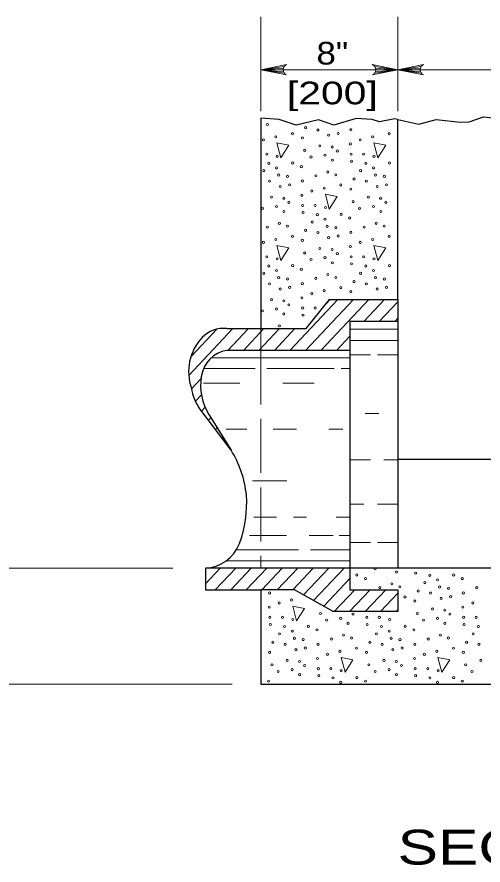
# Model space of a CAD drawing. Extents: x -410.5 to -376.5, y 1617.6 to 1661.6.
# Drawn here: x -396.46 to -393.25, y 1628.9 to 1634.74 of the extents above; entities that cross this region are included whole.
import ezdxf
from ezdxf.enums import TextEntityAlignment as Align

# ---------------------------------------------------------------- set-up
doc = ezdxf.new("R2010")
doc.units = 0
doc.header["$LTSCALE"] = 0.062
doc.linetypes.add('LONG_DASHED', pattern=[7.5, 6, -1.5])
doc.layers.add('1', color=7, linetype='Continuous', lineweight=13)

msp = doc.modelspace()

# ---------------------------------------------------------------- linework, layer by layer
at = {"layer": '1'}
for p, q in [((-394.77725, 1634.09325), (-394.77725, 1634.74117)), ((-393.83325, 1634.09325), (-393.83325, 1634.74117)), ((-394.617, 1634.40017), (-394.77725, 1634.37775)), ((-394.62242, 1634.38908), (-394.77725, 1634.37775)), ((-394.77725, 1634.37775), (-393.83325, 1634.37775)), ((-394.62408, 1634.37775), (-394.77725, 1634.37775)), ((-394.62125, 1634.36333), (-394.77725, 1634.37775)), ((-394.61517, 1634.353), (-394.77725, 1634.37775)), ((-394.06658, 1634.37775), (-393.83325, 1634.37775)), ((-393.99542, 1634.353), (-393.83325, 1634.37775)), ((-393.9935, 1634.40017), (-393.83325, 1634.37775)), ((-393.98925, 1634.36333), (-393.83325, 1634.37775)), ((-393.98808, 1634.38908), (-393.83325, 1634.37775)), ((-393.98642, 1634.37775), (-393.83325, 1634.37775)), ((-393.673, 1634.40017), (-393.83325, 1634.37775)), ((-393.67842, 1634.38908), (-393.83325, 1634.37775)), ((-393.83325, 1634.37775), (-391.91983, 1634.37775)), ((-393.68008, 1634.37775), (-393.83325, 1634.37775)), ((-393.67725, 1634.36333), (-393.83325, 1634.37775)), ((-393.67117, 1634.353), (-393.83325, 1634.37775)), ((-394.57767, 1632.44417), (-394.24733, 1632.794)), ((-394.47083, 1632.44417), (-394.1405, 1632.794)), ((-394.36408, 1632.44417), (-394.03367, 1632.794)), ((-394.33008, 1632.76292), (-394.30067, 1632.794)), ((-394.2535, 1632.794), (-394.25125, 1632.79767)), ((-394.0685, 1632.64408), (-393.927, 1632.794)), ((-393.96175, 1632.64408), (-393.83333, 1632.78)), ((-393.85492, 1632.64408), (-393.83333, 1632.66692)), ((-395.275, 1632.27142), (-394.97008, 1632.59408)), ((-395.26075, 1632.3995), (-395.07883, 1632.592)), ((-395.00492, 1632.44417), (-394.86325, 1632.59408)), ((-394.89808, 1632.44417), (-394.7565, 1632.59408)), ((-394.79125, 1632.44417), (-394.64975, 1632.59408)), ((-394.77725, 1632.59408), (-394.77725, 1632.44417)), ((-394.6845, 1632.44417), (-394.54292, 1632.59408)), ((-394.16367, 1632.58983), (-393.83325, 1632.58983)), ((-394.25725, 1632.44417), (-394.16367, 1632.54333)), ((-394.16367, 1632.51233), (-393.83325, 1632.51233)), ((-395.11875, 1632.39425), (-394.16367, 1632.39425)), ((-394.16367, 1632.414), (-394.02208, 1632.414)), ((-393.97483, 1632.414), (-393.83325, 1632.414)), ((-395.1725, 1632.31925), (-394.81608, 1632.31925)), ((-394.73783, 1632.31925), (-394.27367, 1632.31925)), ((-394.22475, 1632.31925), (-394.16367, 1632.31925)), ((-395.25542, 1632.17892), (-395.19075, 1632.2475)), ((-395.1725, 1632.21933), (-394.92358, 1632.21933)), ((-394.62542, 1632.21933), (-394.41042, 1632.21933)), ((-395.22967, 1632.09317), (-395.18725, 1632.138)), ((-395.18625, 1632.026), (-395.16167, 1632.05217)), ((-395.13883, 1631.96325), (-395.12217, 1631.98092)), ((-394.05858, 1632.01042), (-393.96417, 1632.01042)), ((-395.09133, 1631.90042), (-395.07975, 1631.91267)), ((-395.01642, 1631.90175), (-394.87483, 1631.90175)), ((-394.69392, 1631.90175), (-394.53258, 1631.90175)), ((-394.30842, 1631.90175), (-394.214, 1631.90175)), ((-395.04383, 1631.8375), (-395.03742, 1631.84442)), ((-395.02008, 1631.80617), (-395.01617, 1631.81033)), ((-394.99633, 1631.77475), (-394.995, 1631.77625)), ((-394.16367, 1631.68967), (-394.02208, 1631.68967)), ((-393.92992, 1631.68967), (-393.83558, 1631.68967)), ((-394.83567, 1631.54483), (-394.59967, 1631.54483)), ((-394.06925, 1631.38442), (-394.16367, 1631.38442)), ((-393.97483, 1631.38442), (-393.83325, 1631.38442)), ((-394.82583, 1631.29483), (-394.66942, 1631.29483)), ((-394.55217, 1631.29483), (-394.46417, 1631.29483)), ((-394.25892, 1631.29483), (-394.16367, 1631.29483)), ((-394.85517, 1631.16992), (-394.60108, 1631.16992)), ((-394.44467, 1631.16992), (-394.2785, 1631.16992)), ((-394.23942, 1631.16992), (-394.16367, 1631.16992)), ((-394.02208, 1631.1205), (-394.16367, 1631.1205)), ((-393.97483, 1631.1205), (-393.83325, 1631.1205)), ((-394.94808, 1631.07), (-394.518, 1631.07)), ((-394.43492, 1631.07), (-394.16367, 1631.07)), ((-395.01733, 1630.995), (-394.16367, 1630.995)), ((-395.38492, 1630.94508), (-400.5225, 1630.94508)), ((-395.15917, 1630.8375), (-395.05767, 1630.94508)), ((-395.0925, 1630.79517), (-394.95083, 1630.94508)), ((-394.98567, 1630.79517), (-394.84408, 1630.94508)), ((-394.87883, 1630.79517), (-394.73725, 1630.94508)), ((-394.77208, 1630.79517), (-394.6305, 1630.94508)), ((-394.66525, 1630.79517), (-394.52375, 1630.94508)), ((-394.5585, 1630.79517), (-394.41692, 1630.94508)), ((-394.48425, 1630.76067), (-394.31008, 1630.94508)), ((-394.4145, 1630.72133), (-394.20333, 1630.94508)), ((-394.34483, 1630.68208), (-394.16367, 1630.87383)), ((-394.27283, 1630.64525), (-394.13125, 1630.79517)), ((-394.166, 1630.64525), (-394.02442, 1630.79517)), ((-394.05917, 1630.64525), (-393.91767, 1630.79517)), ((-393.95242, 1630.64525), (-393.83333, 1630.77133)), ((-393.84558, 1630.64525), (-393.83333, 1630.65833)), ((-400.5225, 1630.1455), (-394.97567, 1630.1455))]:
    msp.add_line(p, q, dxfattribs=at)
at = {"layer": '1', "lineweight": 25}
for p, q in [((-394.77725, 1634.04325), (-394.77725, 1632.59408)), ((-393.83325, 1632.64408), (-393.83325, 1630.94508)), ((-394.16367, 1632.44417), (-394.16367, 1630.94508)), ((-394.98333, 1631.75742), (-395.20567, 1632.05158)), ((-395.13633, 1632.00358), (-394.98333, 1631.75742)), ((-393.83325, 1631.69458), (-391.09567, 1631.69458)), ((-395.15925, 1630.94508), (-395.15925, 1630.79517))]:
    msp.add_line(p, q, dxfattribs=at)
at = {"layer": '1', "linetype": 'LONG_DASHED'}
msp.add_line((-394.77725, 1632.44417), (-394.77725, 1630.94508), dxfattribs=at)
at = {"layer": '1'}
for points in [[(-394.60025, 1634.34233), (-394.77725, 1634.37775), (-394.60025, 1634.41317)], [(-394.01025, 1634.34233), (-393.83325, 1634.37775), (-394.01025, 1634.41317)], [(-393.65625, 1634.34233), (-393.83325, 1634.37775), (-393.65625, 1634.41317)]]:
    msp.add_lwpolyline(points, dxfattribs=at)
at = {"layer": '1', "lineweight": 25}
for points in [[(-393.83325, 1634.03533), (-393.85467, 1634.04017), (-393.96075, 1634.01817), (-394.011, 1634.0345), (-394.12183, 1634.04083), (-394.27542, 1633.99475), (-394.38142, 1634.03242), (-394.53508, 1633.99542), (-394.6515, 1634.03517), (-394.77725, 1634.04325)], [(-394.77725, 1632.59408), (-394.46475, 1632.59408), (-394.30525, 1632.794), (-393.83325, 1632.794), (-393.83325, 1634.03533)], [(-393.83325, 1634.03533), (-393.68983, 1634.00333), (-393.57033, 1634.03433), (-393.40175, 1634.01567), (-393.34308, 1634.0185), (-393.2425, 1634.05275), (-393.18192, 1634.0455), (-393.12783, 1634.04333), (-392.90825, 1634.00433), (-392.75167, 1634.05242), (-392.54808, 1634.03167), (-392.37933, 1634.06567), (-392.26933, 1634.0725), (-392.08858, 1634.01725), (-391.91983, 1634.04825), (-391.69733, 1634.01025), (-391.53892, 1634.04625), (-391.48967, 1634.05725), (-391.23017, 1634.01908), (-391.09567, 1634.05167)], [(-395.01325, 1632.59408), (-394.46475, 1632.59408), (-394.30525, 1632.794), (-393.83325, 1632.794), (-393.83325, 1632.64408), (-394.16367, 1632.64408), (-394.16367, 1632.44417), (-395.01325, 1632.44417)], [(-394.16367, 1630.94508), (-394.77725, 1630.94508), (-395.15925, 1630.94508)], [(-395.15925, 1630.79517), (-394.77725, 1630.79517), (-394.77725, 1630.1455), (-390.15167, 1630.1455), (-390.15167, 1630.94508), (-394.16367, 1630.94508), (-394.16367, 1630.79517), (-393.83325, 1630.79517), (-393.83325, 1630.64525), (-394.27908, 1630.64525), (-394.54583, 1630.79517), (-394.77725, 1630.79517)]]:
    msp.add_lwpolyline(points, dxfattribs=at)
at = {"layer": '1'}
for points in [[(-394.66692, 1633.87358), (-394.63992, 1633.77117), (-394.58492, 1633.85767)], [(-393.99942, 1633.87358), (-393.97242, 1633.77117), (-393.91742, 1633.85767)], [(-394.33308, 1633.52025), (-394.30617, 1633.41792), (-394.25125, 1633.50433)], [(-394.66692, 1633.16692), (-394.63992, 1633.0645), (-394.58492, 1633.15092)], [(-393.99942, 1633.16692), (-393.97242, 1633.0645), (-393.91742, 1633.15092)], [(-394.55867, 1630.68292), (-394.53167, 1630.58042), (-394.47675, 1630.66692)], [(-394.22492, 1630.3295), (-394.198, 1630.22717), (-394.143, 1630.31358)], [(-393.55742, 1630.3295), (-393.53042, 1630.22717), (-393.4755, 1630.31358)]]:
    msp.add_lwpolyline(points, close=True, dxfattribs=at)
for centre, start, end in [((-394.58597, 1634.3778), 112.08782, 247.91395), ((-394.02456, 1634.3778), 292.08605, 67.91218), ((-393.64197, 1634.3778), 112.08782, 247.91395)]:
    msp.add_arc(centre, 0.0382, start, end, dxfattribs=at)
for centre, major_axis in [((-394.73353, 1634.00018), (0, -0.00756)), ((-394.46947, 1633.97822), (0, 0.00756)), ((-394.38448, 1633.96326), (0, 0.00756)), ((-394.15825, 1633.96414), (0, -0.00756)), ((-394.76062, 1633.89518), (0, -0.00756)), ((-394.67495, 1633.9152), (0, -0.00756)), ((-394.56053, 1633.93717), (0, 0.00756)), ((-394.492, 1633.90855), (0, 0.00756)), ((-394.3106, 1633.92698), (0, 0.00756)), ((-394.24569, 1633.93847), (0, -0.00756)), ((-394.09311, 1633.89518), (0, -0.00756)), ((-394.00744, 1633.9152), (0, -0.00756)), ((-393.89302, 1633.93717), (0, 0.00756)), ((-394.37124, 1633.85325), (0, 0.00756)), ((-394.28619, 1633.84589), (0, 0.00756)), ((-394.16153, 1633.86656), (0, -0.00756)), ((-394.73709, 1633.79595), (0, 0.00756)), ((-394.66594, 1633.78164), (0, -0.00756)), ((-394.47576, 1633.82268), (0, 0.00756)), ((-394.43248, 1633.77687), (0, 0.00756)), ((-394.33608, 1633.78929), (0, 0.00756)), ((-394.25075, 1633.81791), (0, -0.00756)), ((-394.15613, 1633.79595), (0, -0.00756)), ((-394.06958, 1633.79595), (0, 0.00756)), ((-393.99843, 1633.78164), (0, -0.00756)), ((-394.72268, 1633.73299), (0, 0.00756)), ((-394.5587, 1633.73488), (0, -0.00756)), ((-394.2853, 1633.75461), (0, -0.00756)), ((-394.15346, 1633.7473), (0, -0.00756)), ((-394.05517, 1633.73299), (0, 0.00756)), ((-393.89119, 1633.73488), (0, -0.00756)), ((-394.75789, 1633.6824), (0, 0.00756)), ((-394.66956, 1633.70149), (0, 0.00756)), ((-394.49923, 1633.71008), (0, -0.00756)), ((-394.31683, 1633.67351), (0, -0.00756)), ((-394.09038, 1633.6824), (0, 0.00756)), ((-394.00205, 1633.70149), (0, 0.00756)), ((-394.71823, 1633.60991), (0, 0.00756)), ((-394.65509, 1633.6519), (0, 0.00756)), ((-394.59474, 1633.64324), (0, -0.00756)), ((-394.492, 1633.61079), (0, -0.00756)), ((-394.39977, 1633.64683), (0, -0.00756)), ((-394.26188, 1633.65349), (0, -0.00756)), ((-394.13572, 1633.62487), (0, 0.00756)), ((-394.05072, 1633.60991), (0, 0.00756)), ((-393.98759, 1633.6519), (0, 0.00756)), ((-393.92723, 1633.64324), (0, -0.00756)), ((-394.64436, 1633.57363), (0, 0.00756)), ((-394.57944, 1633.58512), (0, -0.00756)), ((-394.3412, 1633.56185), (0, -0.00756)), ((-394.22678, 1633.58382), (0, 0.00756)), ((-394.15825, 1633.5552), (0, 0.00756)), ((-393.97685, 1633.57363), (0, 0.00756)), ((-393.91194, 1633.58512), (0, -0.00756)), ((-394.70499, 1633.4999), (0, 0.00756)), ((-394.61994, 1633.49254), (0, 0.00756)), ((-394.49528, 1633.51321), (0, -0.00756)), ((-394.42686, 1633.54183), (0, -0.00756)), ((-394.03748, 1633.4999), (0, 0.00756)), ((-393.95243, 1633.49254), (0, 0.00756)), ((-394.66984, 1633.43594), (0, 0.00756)), ((-394.58451, 1633.46456), (0, -0.00756)), ((-394.48989, 1633.4426), (0, -0.00756)), ((-394.40333, 1633.4426), (0, 0.00756)), ((-394.33219, 1633.42829), (0, -0.00756)), ((-394.142, 1633.46933), (0, 0.00756)), ((-394.00233, 1633.43594), (0, 0.00756)), ((-393.917, 1633.46456), (0, -0.00756)), ((-394.76623, 1633.42352), (0, 0.00756)), ((-394.61905, 1633.40126), (0, -0.00756)), ((-394.48722, 1633.39395), (0, -0.00756)), ((-394.38893, 1633.37964), (0, 0.00756)), ((-394.22494, 1633.38153), (0, -0.00756)), ((-394.09873, 1633.42352), (0, 0.00756)), ((-393.95154, 1633.40126), (0, -0.00756)), ((-394.65059, 1633.32016), (0, -0.00756)), ((-394.42414, 1633.32906), (0, 0.00756)), ((-394.3358, 1633.34814), (0, 0.00756)), ((-394.16548, 1633.35673), (0, -0.00756)), ((-393.98308, 1633.32016), (0, -0.00756)), ((-394.73353, 1633.29348), (0, -0.00756)), ((-394.59563, 1633.30014), (0, -0.00756)), ((-394.46947, 1633.27152), (0, 0.00756)), ((-394.38448, 1633.25656), (0, 0.00756)), ((-394.32134, 1633.29855), (0, 0.00756)), ((-394.26099, 1633.28989), (0, -0.00756)), ((-394.15825, 1633.25744), (0, -0.00756)), ((-394.06602, 1633.29348), (0, -0.00756)), ((-393.92812, 1633.30014), (0, -0.00756)), ((-394.67495, 1633.2085), (0, -0.00756)), ((-394.56053, 1633.23047), (0, 0.00756)), ((-394.492, 1633.20185), (0, 0.00756)), ((-394.3106, 1633.22028), (0, 0.00756)), ((-394.24569, 1633.23177), (0, -0.00756)), ((-394.00744, 1633.2085), (0, -0.00756)), ((-393.89302, 1633.23047), (0, 0.00756)), ((-394.76062, 1633.18848), (0, -0.00756)), ((-394.37124, 1633.14655), (0, 0.00756)), ((-394.28619, 1633.13919), (0, 0.00756)), ((-394.16153, 1633.15986), (0, -0.00756)), ((-394.09311, 1633.18848), (0, -0.00756)), ((-394.73709, 1633.08925), (0, 0.00756)), ((-394.47576, 1633.11599), (0, 0.00756)), ((-394.33608, 1633.08259), (0, 0.00756)), ((-394.25075, 1633.11121), (0, -0.00756)), ((-394.15613, 1633.08925), (0, -0.00756)), ((-394.06958, 1633.08925), (0, 0.00756)), ((-394.72268, 1633.02629), (0, 0.00756)), ((-394.66594, 1633.07494), (0, -0.00756)), ((-394.5587, 1633.02818), (0, -0.00756)), ((-394.43248, 1633.07017), (0, 0.00756)), ((-394.2853, 1633.04791), (0, -0.00756)), ((-394.15346, 1633.0406), (0, -0.00756)), ((-394.05517, 1633.02629), (0, 0.00756)), ((-393.99843, 1633.07494), (0, -0.00756)), ((-393.89119, 1633.02818), (0, -0.00756)), ((-394.75789, 1632.97571), (0, 0.00756)), ((-394.66956, 1632.99479), (0, 0.00756)), ((-394.49923, 1633.00338), (0, -0.00756)), ((-394.31683, 1632.96681), (0, -0.00756)), ((-394.09038, 1632.97571), (0, 0.00756)), ((-394.00205, 1632.99479), (0, 0.00756)), ((-394.71823, 1632.90321), (0, 0.00756)), ((-394.65509, 1632.9452), (0, 0.00756)), ((-394.59474, 1632.93654), (0, -0.00756)), ((-394.492, 1632.90409), (0, -0.00756)), ((-394.39977, 1632.94013), (0, -0.00756)), ((-394.26188, 1632.94679), (0, -0.00756)), ((-394.13572, 1632.91817), (0, 0.00756)), ((-394.05072, 1632.90321), (0, 0.00756)), ((-393.98759, 1632.9452), (0, 0.00756)), ((-393.92723, 1632.93654), (0, -0.00756)), ((-394.64436, 1632.86693), (0, 0.00756)), ((-394.57944, 1632.87842), (0, -0.00756)), ((-394.3412, 1632.85515), (0, -0.00756)), ((-394.22678, 1632.87712), (0, 0.00756)), ((-394.15825, 1632.8485), (0, 0.00756)), ((-393.97685, 1632.86693), (0, 0.00756)), ((-393.91194, 1632.87842), (0, -0.00756)), ((-394.70499, 1632.7932), (0, 0.00756)), ((-394.61994, 1632.78584), (0, 0.00756)), ((-394.49528, 1632.80651), (0, -0.00756)), ((-394.42686, 1632.83513), (0, -0.00756)), ((-394.66984, 1632.72924), (0, 0.00756)), ((-394.58451, 1632.75787), (0, -0.00756)), ((-394.48989, 1632.7359), (0, -0.00756)), ((-394.40333, 1632.7359), (0, 0.00756)), ((-394.76623, 1632.71682), (0, 0.00756)), ((-394.61905, 1632.69456), (0, -0.00756)), ((-394.48722, 1632.68725), (0, -0.00756)), ((-394.65059, 1632.61346), (0, -0.00756)), ((-393.9905, 1630.93945), (0, 0.00756)), ((-393.84332, 1630.91719), (0, -0.00756)), ((-394.11672, 1630.89746), (0, -0.00756)), ((-394.05725, 1630.87267), (0, -0.00756)), ((-393.71148, 1630.90989), (0, -0.00756)), ((-393.61319, 1630.89558), (0, 0.00756)), ((-393.56007, 1630.86407), (0, 0.00756)), ((-393.44921, 1630.89746), (0, -0.00756)), ((-393.38974, 1630.87267), (0, -0.00756)), ((-393.95779, 1630.80942), (0, -0.00756)), ((-393.87486, 1630.83609), (0, -0.00756)), ((-393.8199, 1630.81607), (0, -0.00756)), ((-393.6484, 1630.84499), (0, 0.00756)), ((-393.54561, 1630.81448), (0, 0.00756)), ((-393.48525, 1630.80582), (0, -0.00756)), ((-393.29028, 1630.80942), (0, -0.00756)), ((-394.71753, 1630.77338), (0, -0.00756)), ((-393.7848, 1630.7464), (0, 0.00756)), ((-393.69374, 1630.78745), (0, 0.00756)), ((-393.60874, 1630.77249), (0, 0.00756)), ((-393.46996, 1630.7477), (0, -0.00756)), ((-393.38251, 1630.77338), (0, -0.00756)), ((-394.65239, 1630.70441), (0, -0.00756)), ((-394.56673, 1630.72444), (0, -0.00756)), ((-393.71627, 1630.71778), (0, 0.00756)), ((-393.53487, 1630.73621), (0, 0.00756)), ((-393.31737, 1630.70441), (0, -0.00756)), ((-394.72081, 1630.67579), (0, -0.00756)), ((-394.36753, 1630.63192), (0, 0.00756)), ((-394.14253, 1630.62715), (0, -0.00756)), ((-393.70002, 1630.63192), (0, 0.00756)), ((-393.5955, 1630.66248), (0, 0.00756)), ((-393.51045, 1630.65512), (0, 0.00756)), ((-393.47502, 1630.62715), (0, -0.00756)), ((-393.38579, 1630.67579), (0, -0.00756)), ((-394.71542, 1630.60518), (0, -0.00756)), ((-394.62886, 1630.60518), (0, 0.00756)), ((-394.55772, 1630.59087), (0, -0.00756)), ((-394.32426, 1630.5861), (0, 0.00756)), ((-394.22786, 1630.59853), (0, 0.00756)), ((-394.17707, 1630.56384), (0, -0.00756)), ((-394.04791, 1630.60518), (0, -0.00756)), ((-393.96135, 1630.60518), (0, 0.00756)), ((-393.89021, 1630.59087), (0, -0.00756)), ((-393.65675, 1630.5861), (0, 0.00756)), ((-393.56035, 1630.59853), (0, 0.00756)), ((-393.50956, 1630.56384), (0, -0.00756)), ((-393.3804, 1630.60518), (0, -0.00756)), ((-393.29384, 1630.60518), (0, 0.00756)), ((-394.71275, 1630.55654), (0, -0.00756)), ((-394.61445, 1630.54223), (0, 0.00756)), ((-394.56133, 1630.51072), (0, 0.00756)), ((-394.45047, 1630.54411), (0, -0.00756)), ((-394.39101, 1630.51932), (0, -0.00756)), ((-394.04524, 1630.55654), (0, -0.00756)), ((-393.94695, 1630.54223), (0, 0.00756)), ((-393.89382, 1630.51072), (0, 0.00756)), ((-393.78296, 1630.54411), (0, -0.00756)), ((-393.7235, 1630.51932), (0, -0.00756)), ((-393.37773, 1630.55654), (0, -0.00756)), ((-393.27944, 1630.54223), (0, 0.00756)), ((-394.64967, 1630.49164), (0, 0.00756)), ((-394.54687, 1630.46113), (0, 0.00756)), ((-394.48652, 1630.45247), (0, -0.00756)), ((-394.29155, 1630.45607), (0, -0.00756)), ((-394.20861, 1630.48274), (0, -0.00756)), ((-394.15365, 1630.46272), (0, -0.00756)), ((-393.98216, 1630.49164), (0, 0.00756)), ((-393.87936, 1630.46113), (0, 0.00756)), ((-393.81901, 1630.45247), (0, -0.00756)), ((-393.62404, 1630.45607), (0, -0.00756)), ((-393.5411, 1630.48274), (0, -0.00756)), ((-393.48614, 1630.46272), (0, -0.00756)), ((-393.31465, 1630.49164), (0, 0.00756)), ((-394.695, 1630.4341), (0, 0.00756)), ((-394.61, 1630.41914), (0, 0.00756)), ((-394.47122, 1630.39435), (0, -0.00756)), ((-394.38377, 1630.42003), (0, -0.00756)), ((-394.11855, 1630.39305), (0, 0.00756)), ((-394.02749, 1630.4341), (0, 0.00756)), ((-393.9425, 1630.41914), (0, 0.00756)), ((-393.80371, 1630.39435), (0, -0.00756)), ((-393.71627, 1630.42003), (0, -0.00756)), ((-393.45104, 1630.39305), (0, 0.00756)), ((-393.35998, 1630.4341), (0, 0.00756)), ((-393.27499, 1630.41914), (0, 0.00756)), ((-394.71753, 1630.36443), (0, 0.00756)), ((-394.53613, 1630.38286), (0, 0.00756)), ((-394.31864, 1630.35106), (0, -0.00756)), ((-394.23297, 1630.37109), (0, -0.00756)), ((-394.05002, 1630.36443), (0, 0.00756)), ((-393.86863, 1630.38286), (0, 0.00756)), ((-393.65113, 1630.35106), (0, -0.00756)), ((-393.56547, 1630.37109), (0, -0.00756)), ((-393.38251, 1630.36443), (0, 0.00756)), ((-394.70129, 1630.27857), (0, 0.00756)), ((-394.59677, 1630.30913), (0, 0.00756)), ((-394.51171, 1630.30177), (0, 0.00756)), ((-394.47628, 1630.2738), (0, -0.00756)), ((-394.38706, 1630.32244), (0, -0.00756)), ((-394.03378, 1630.27857), (0, 0.00756)), ((-393.92926, 1630.30913), (0, 0.00756)), ((-393.84421, 1630.30177), (0, 0.00756)), ((-393.80877, 1630.2738), (0, -0.00756)), ((-393.71955, 1630.32244), (0, -0.00756)), ((-393.36627, 1630.27857), (0, 0.00756)), ((-393.26175, 1630.30913), (0, 0.00756)), ((-394.65801, 1630.23275), (0, 0.00756)), ((-394.56161, 1630.24518), (0, 0.00756)), ((-394.38166, 1630.25183), (0, -0.00756)), ((-394.29511, 1630.25183), (0, 0.00756)), ((-394.22396, 1630.23752), (0, -0.00756)), ((-393.9905, 1630.23275), (0, 0.00756)), ((-393.8941, 1630.24518), (0, 0.00756)), ((-393.71415, 1630.25183), (0, -0.00756)), ((-393.6276, 1630.25183), (0, 0.00756)), ((-393.55645, 1630.23752), (0, -0.00756)), ((-393.32299, 1630.23275), (0, 0.00756)), ((-394.72476, 1630.16597), (0, -0.00756)), ((-394.51082, 1630.21049), (0, -0.00756)), ((-394.37899, 1630.20319), (0, -0.00756)), ((-394.2807, 1630.18888), (0, 0.00756)), ((-394.22758, 1630.15737), (0, 0.00756)), ((-394.11672, 1630.19076), (0, -0.00756)), ((-394.05725, 1630.16597), (0, -0.00756)), ((-393.84332, 1630.21049), (0, -0.00756)), ((-393.71148, 1630.20319), (0, -0.00756)), ((-393.61319, 1630.18888), (0, 0.00756)), ((-393.56007, 1630.15737), (0, 0.00756)), ((-393.44921, 1630.19076), (0, -0.00756)), ((-393.38974, 1630.16597), (0, -0.00756))]:
    msp.add_ellipse(centre, major_axis=major_axis, ratio=0.944543, dxfattribs=at)
at = {"layer": '1', "lineweight": 25}
for centre, major_axis, start_param, end_param in [((-395.04019, 1632.38668), (0, -0.20938), 3.0050305, 3.9444684), ((-394.96841, 1632.29815), (0, 0.32575), 0.7694236, 1.9339738), ((-394.9851, 1632.22779), (0, 0.21845), 0.1369091, 1.412149), ((-394.84759, 1632.20468), (0, 0.36587), 1.4126518, 2.1526333), ((-394.98771, 1632.22188), (0, 0.2868), 1.7087867, 2.2065169), ((-395.54573, 1631.3658), (0, 0.71266), 4.8281314, 5.2942094), ((-395.6285, 1631.39924), (0, -0.79703), 1.2047509, 1.6321425), ((-395.16844, 1631.22498), (0, -0.28009), 0.0346617, 1.163241)]:
    msp.add_ellipse(centre, major_axis=major_axis, ratio=0.944543, start_param=start_param, end_param=end_param, dxfattribs=at)

# ---------------------------------------------------------------- texts
at = {"layer": '1'}
for s, width, p in [('8"', 1.15, (-394.28533, 1634.41342)), ('[200]', 1.35, (-394.28533, 1634.13942))]:
    msp.add_text(s, height=0.156, dxfattribs=dict(at, width=width)).set_placement(p, align=Align.CENTER)
at = {"layer": '1', "width": 1.3}
msp.add_text('SECTION B-B', height=0.24, dxfattribs=at).set_placement((-393.83558, 1628.90275))

doc.saveas('drawing.dxf')
